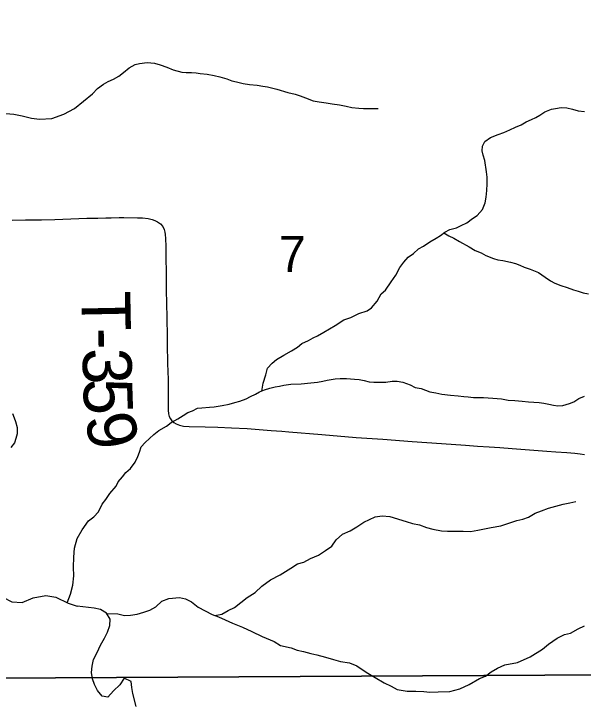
# Model space of a CAD drawing. Extents: x 1985906 to 2360102, y 891258 to 1222054.
# Drawn here: x 2141197 to 2144687, y 1014690 to 1018920 of the extents above; entities that cross this region are included whole.
import ezdxf

# ---------------------------------------------------------------- set-up
doc = ezdxf.new("R2010")
doc.units = 0
for name, color, linetype in [('GM_X_Minor_River', 7, 'Continuous'), ('GM_X_Section', 7, 'Continuous'), ('GM_X_Section_Text', 7, 'Continuous'), ('GM_X_Township_Road', 7, 'Continuous'), ('GM_X_Township_Road_Text', 7, 'Continuous')]:
    doc.layers.add(name, color=color, linetype=linetype)

msp = doc.modelspace()

# ---------------------------------------------------------------- linework, layer by layer
at = {"layer": 'GM_X_Minor_River'}
for points in [[(2141570.3, 1018340.4), (2141678.8, 1018430.1), (2141710.7, 1018462.5), (2141746.6, 1018488.9), (2141776.6, 1018505.2), (2141808.6, 1018519.5), (2141840.5, 1018537.9), (2141870.5, 1018560.2), (2141904.3, 1018588.6), (2141940.3, 1018608.9), (2141968.4, 1018615.2), (2142014.5, 1018621.6), (2142058.7, 1018617.9), (2142094.9, 1018606.2), (2142135.2, 1018592.5), (2142173.5, 1018576.7), (2142227.8, 1018563.1), (2142253.9, 1018559.3), (2142286, 1018559.6), (2142314.2, 1018557.8), (2142340.3, 1018554), (2142382.5, 1018550.3), (2142424.7, 1018542.6), (2142460.9, 1018532.9), (2142503.2, 1018521.2), (2142533.4, 1018509.4), (2142561.6, 1018503.6), (2142603.8, 1018491.9), (2142642, 1018486.2), (2142688.2, 1018482.6), (2142724.4, 1018476.8), (2142752.5, 1018473), (2142808.9, 1018457.4), (2142877.3, 1018437.9), (2142921.6, 1018428.2), (2142951.8, 1018416.4), (2142986, 1018404.7), (2143032.3, 1018387), (2143068.5, 1018381.3), (2143112.7, 1018373.6), (2143148.9, 1018367.9), (2143193.2, 1018362.2), (2143235.4, 1018354.5), (2143269.6, 1018346.8), (2143311.8, 1018341.1), (2143339.9, 1018339.3), (2143430.2, 1018340)], [(2141040.7, 1018290.3), (2141070.7, 1018298.6), (2141124.6, 1018311), (2141196.6, 1018305.5), (2141248.7, 1018293.9), (2141304.8, 1018280.3), (2141354.8, 1018274.7), (2141430.8, 1018279.3), (2141504.6, 1018305.9), (2141570.3, 1018340.4)], [(2142716.9, 1016608.6), (2142725.8, 1016657.8), (2142741.4, 1016708.1), (2142753.1, 1016748.4), (2142781, 1016778.7), (2142806.9, 1016801), (2142852.8, 1016827.5), (2142898.8, 1016856), (2142936.7, 1016878.4), (2142962.6, 1016900.7), (2143002.6, 1016919.1), (2143032.6, 1016935.4), (2143058.6, 1016947.6), (2143096.6, 1016970), (2143166.5, 1017010.8), (2143220.4, 1017045.3), (2143262.4, 1017059.7), (2143312.4, 1017084.2), (2143362.5, 1017100.7), (2143390.4, 1017119), (2143424.2, 1017159.4), (2143449.9, 1017203.8), (2143475.8, 1017226.1), (2143509.5, 1017278.6), (2143539.3, 1017319), (2143563, 1017365.4), (2143588.8, 1017397.7), (2143614.7, 1017428), (2143646.6, 1017450.4), (2143678.5, 1017480.7), (2143708.4, 1017497), (2143748.3, 1017523.5), (2143786.3, 1017545.9), (2143812.3, 1017562.2), (2143840.2, 1017582.4), (2143870.2, 1017598.8), (2143910.2, 1017609.1), (2143940.2, 1017623.4), (2143974.2, 1017639.8), (2144008.1, 1017666.2), (2144038.1, 1017684.5), (2144069.9, 1017720.9), (2144085.6, 1017761.2), (2144093.3, 1017797.3), (2144097, 1017837.5), (2144098.7, 1017877.7), (2144098.3, 1017919.9), (2144094, 1017951.9), (2144085.4, 1018020.1), (2144075.1, 1018054.2), (2144068.9, 1018080.2), (2144070.6, 1018108.4), (2144084.4, 1018136.6), (2144118.4, 1018161), (2144166.4, 1018179.4), (2144200.4, 1018191.8), (2144238.4, 1018208.1), (2144272.4, 1018224.5), (2144306.4, 1018238.8), (2144338.4, 1018257.1), (2144370.4, 1018271.4), (2144396.4, 1018283.7), (2144422.4, 1018298), (2144452.3, 1018318.3), (2144492.3, 1018334.7), (2144518.4, 1018338.9), (2144552.5, 1018345.2), (2144586.6, 1018343.5), (2144620.8, 1018335.7), (2144657, 1018326), (2144695.2, 1018320.3)], [(2143833, 1017577.2), (2143864.5, 1017558.6), (2143894.7, 1017544.8), (2143929, 1017525), (2143987.5, 1017491.3), (2144025.9, 1017469.5), (2144062.1, 1017455.8), (2144090.4, 1017439.9), (2144136.7, 1017420.2), (2144164.9, 1017412.4), (2144195, 1017408.7), (2144241.3, 1017399), (2144271.5, 1017389.2), (2144299.7, 1017379.4), (2144325.9, 1017367.6), (2144362.1, 1017355.8), (2144412.5, 1017334.2), (2144454.9, 1017306.4), (2144487.2, 1017284.6), (2144513.4, 1017268.7), (2144549.7, 1017255), (2144589.9, 1017243.2), (2144628.2, 1017229.5), (2144656.4, 1017219.7), (2144686.6, 1017209.9), (2144720.7, 1017204.2)], [(2141615.5, 1015759), (2141655.6, 1015813.7), (2141686.8, 1015838.2), (2141716.7, 1015868.5), (2141738.3, 1015914.9), (2141762.2, 1015945.2), (2141786, 1015981.5), (2141823.7, 1016026), (2141837.6, 1016052.2), (2141863.4, 1016082.5), (2141883.2, 1016108.8), (2141913.2, 1016133.1), (2141940.9, 1016173.5), (2141956.7, 1016207.8), (2141968.5, 1016234), (2141978.3, 1016266.2), (2142002.2, 1016292.5), (2142030, 1016318.8), (2142055.9, 1016343.1), (2142085.8, 1016367.4), (2142133.8, 1016393.9), (2142161.7, 1016416.3), (2142201.7, 1016438.7), (2142235.6, 1016459), (2142263.6, 1016477.3), (2142293.6, 1016487.6), (2142323.6, 1016503.9), (2142349.7, 1016506.1), (2142395.8, 1016510.5), (2142425.9, 1016512.8), (2142474, 1016519.2), (2142518.1, 1016527.6), (2142552.2, 1016537.9), (2142582.2, 1016546.2), (2142622.2, 1016560.6), (2142648.2, 1016574.8), (2142678.2, 1016589.1), (2142704.2, 1016603.4), (2142734.2, 1016615.7), (2142766.2, 1016626), (2142798.3, 1016634.3), (2142826.3, 1016638.5), (2142852.4, 1016644.8), (2142894.5, 1016651.2), (2142958.7, 1016653.7), (2143016.9, 1016658.2), (2143059, 1016662.5), (2143091.1, 1016668.8), (2143117.1, 1016675), (2143167.3, 1016683.5), (2143197.4, 1016685.8), (2143237.5, 1016686.1), (2143285.7, 1016680.4), (2143313.9, 1016678.7), (2143344, 1016672.9), (2143376.2, 1016665.1), (2143404.3, 1016663.3), (2143478.6, 1016664), (2143516.7, 1016668.3), (2143546.8, 1016668.5), (2143581, 1016662.8), (2143627.3, 1016647.1), (2143657.6, 1016631.3), (2143693.8, 1016623.5), (2143748.1, 1016603.9), (2143784.3, 1016598.2), (2143820.5, 1016590.5), (2143874.8, 1016582.9), (2143921, 1016579.2), (2143955.2, 1016575.5), (2143981.3, 1016573.7), (2144015.4, 1016570), (2144075.7, 1016568.4), (2144133.9, 1016564.9), (2144186.2, 1016561.3), (2144226.4, 1016553.6), (2144268.6, 1016549.9), (2144312.8, 1016546.3), (2144352.9, 1016542.6), (2144417.2, 1016539.1), (2144445.4, 1016535.3), (2144477.5, 1016527.6), (2144505.7, 1016521.8), (2144531.8, 1016518), (2144561.9, 1016520.2), (2144604, 1016532.6), (2144630, 1016542.9), (2144659.9, 1016563.2), (2144696, 1016577.5)], [(2141189.7, 1016471.3), (2141200.1, 1016445.3), (2141208.4, 1016421.4), (2141216.9, 1016385.4), (2141217.4, 1016347.3), (2141209.8, 1016317.1), (2141202.1, 1016290.9), (2141178.3, 1016262.5)], [(2142429, 1015234.2), (2142472.8, 1015242.2), (2142510.8, 1015264.6), (2142550.8, 1015283), (2142588.7, 1015313.5), (2142628.6, 1015343.9), (2142676.5, 1015374.4), (2142718.3, 1015412.9), (2142770.2, 1015451.5), (2142830.1, 1015482.1), (2142896, 1015522.8), (2142936, 1015549.2), (2142974, 1015559.6), (2143016, 1015582), (2143064, 1015602.5), (2143107.9, 1015630.9), (2143145.9, 1015657.3), (2143173.6, 1015697.7), (2143211.5, 1015732.2), (2143259.5, 1015752.6), (2143299.4, 1015777), (2143343.4, 1015805.5), (2143411.3, 1015838.2), (2143455.4, 1015844.6), (2143501.7, 1015841), (2143602.3, 1015809.7), (2143640.5, 1015797.9), (2143684.8, 1015788.2), (2143727.1, 1015772.5), (2143765.3, 1015762.8), (2143819.6, 1015753.2), (2143855.8, 1015749.5), (2143952.1, 1015750.3), (2143996.3, 1015748.6), (2144042.4, 1015757), (2144082.5, 1015765.4), (2144122.6, 1015771.7), (2144182.7, 1015782.3), (2144242.8, 1015802.8), (2144280.8, 1015815.2), (2144316.9, 1015823.5), (2144352.9, 1015835.9), (2144392.9, 1015860.3), (2144430.9, 1015874.7), (2144474.9, 1015891.1), (2144519, 1015903.5), (2144565.1, 1015915.9), (2144605.1, 1015924.3), (2144641.2, 1015932.6)], [(2141524.6, 1015311.7), (2141543.9, 1015364.2), (2141559.8, 1015420.3), (2141565.8, 1015476.4), (2141563.7, 1015530.5), (2141565.6, 1015590.6), (2141569.6, 1015646.7), (2141585.5, 1015704.8), (2141615.5, 1015759)], [(2141019.9, 1015413.6), (2141034.5, 1015400.4), (2141131, 1015345.5), (2141185.2, 1015317.9), (2141249.2, 1015312.3), (2141315, 1015340.9), (2141392.9, 1015355.5), (2141454.9, 1015345.9), (2141531.2, 1015308.4), (2141585.3, 1015290.8)], [(2141767.4, 1015246.3), (2141834.4, 1015243), (2141876.6, 1015233.3), (2141912.8, 1015235.7), (2141952.9, 1015242), (2141994.9, 1015254.4), (2142030.9, 1015266.7), (2142066.9, 1015287.1), (2142104.8, 1015321.5), (2142146.8, 1015338), (2142213, 1015344.5), (2142249.2, 1015334.8), (2142285.5, 1015317), (2142327.9, 1015285.2), (2142370.3, 1015261.5), (2142412.6, 1015239.8), (2142452.9, 1015226), (2142493.2, 1015206.3), (2142537.5, 1015186.6), (2142600, 1015163), (2142656.4, 1015135.3), (2142718.9, 1015105.7), (2142793.5, 1015074.2), (2142831.8, 1015050.4), (2142898.2, 1015034.9), (2142934.4, 1015021.2), (2142972.7, 1015013.4), (2143016.9, 1014999.7), (2143055.2, 1014992), (2143107.5, 1014978.4), (2143155.8, 1014964.7), (2143200, 1014951), (2143254.3, 1014943.4), (2143300.6, 1014925.8), (2143357.2, 1014886.1), (2143468.2, 1014820.7), (2143510.5, 1014801), (2143546.8, 1014779.2), (2143609.1, 1014769.7), (2143661.3, 1014770.1), (2143711.5, 1014768.5), (2143747.7, 1014764.8), (2143797.9, 1014765.2), (2143870.1, 1014767.8), (2143930.2, 1014784.3), (2143988.2, 1014810.9), (2144052.1, 1014847.6), (2144088.2, 1014861.9), (2144124.1, 1014888.3), (2144162, 1014910.7), (2144208, 1014931.2), (2144284.2, 1014945.8), (2144362.2, 1014980.6), (2144438.1, 1015027.4), (2144474, 1015057.8), (2144527.9, 1015094.4), (2144571.8, 1015116.9), (2144609.9, 1015125.2), (2144655.9, 1015151.7), (2144695.9, 1015170.1)], [(2141947.6, 1014675.8), (2141926.9, 1014755.9), (2141920.5, 1014792), (2141916.2, 1014830.1), (2141873.9, 1014849.8), (2141848.1, 1014809.5), (2141808.3, 1014771), (2141774.5, 1014732.6), (2141738.3, 1014738.3), (2141709.9, 1014774.2), (2141691.5, 1014810.2), (2141679.2, 1014846.2), (2141672.8, 1014884.3), (2141678.5, 1014922.5), (2141686.2, 1014964.8), (2141707.9, 1015007.1), (2141729.6, 1015051.4), (2141753.4, 1015093.8), (2141771.1, 1015132.1), (2141786.8, 1015172.4), (2141788.5, 1015210.5), (2141766.1, 1015248.5), (2141727.8, 1015270.3), (2141690, 1015278.3), (2141654.3, 1015281.7), (2141585.3, 1015290.8)]]:
    msp.add_lwpolyline(points, dxfattribs=at)
at = {"layer": 'GM_X_Section'}
for points in [[(2141007.1, 1020154.3), (2144733.4, 1020193.5), (2144828.1, 1014870.9), (2141074.1, 1014849.6), (2141073.8, 1014909.6)], [(2141074.1, 1014849.6), (2144828.1, 1014870.9), (2144878.5, 1009582.1), (2141132.9, 1009584.8)]]:
    msp.add_lwpolyline(points, close=True, dxfattribs=at)
at = {"layer": 'GM_X_Township_Road'}
for points in [[(2141187.7, 1017656.4), (2141269.5, 1017656.9), (2141367.5, 1017657.1), (2141449.2, 1017659.7), (2141645.9, 1017667), (2141711.5, 1017668.3), (2141760.7, 1017669), (2141793.5, 1017669.7), (2141842.3, 1017671.2), (2141872.7, 1017672.2), (2141955.8, 1017670.4), (2141987, 1017669.5), (2142020, 1017666), (2142046, 1017659.9), (2142062.5, 1017653.9), (2142079, 1017646), (2142097.3, 1017632.2), (2142110.3, 1017616.5), (2142119, 1017599.1), (2142123.3, 1017582.6), (2142125.9, 1017568.7), (2142126.8, 1017542.7), (2142128.5, 1017493.2), (2142129.4, 1017422), (2142130.2, 1017336.1), (2142130.9, 1017263.1), (2142131.6, 1017220.6), (2142132.9, 1017150.3), (2142134.6, 1017053), (2142136.5, 1016947), (2142137.8, 1016874.1), (2142139.1, 1016800.3), (2142139.5, 1016777.3), (2142142.6, 1016679.2), (2142142.6, 1016564.2), (2142143.4, 1016515), (2142143.9, 1016491.2), (2142145.7, 1016469.1), (2142150.4, 1016453.6), (2142157.5, 1016439.1), (2142166.2, 1016426.7), (2142177.3, 1016416.6), (2142192.1, 1016406.8), (2142213.3, 1016398.8), (2142237.2, 1016393.7), (2142271.2, 1016391.3), (2142370.4, 1016390.3), (2142447.7, 1016388.2), (2142531.2, 1016383.6), (2142627.3, 1016378.3), (2142774, 1016366.6), (2142839.4, 1016362.7), (2142883.9, 1016359)], [(2142883.9, 1016359), (2143084.4, 1016342.5), (2143296.4, 1016324.9), (2143459.9, 1016313.9), (2143639.7, 1016300.1), (2143819.6, 1016288.1), (2143966.6, 1016277.2), (2144039.4, 1016271.9), (2144110.7, 1016266.7), (2144177.3, 1016261.8), (2144252.9, 1016256.2), (2144330.9, 1016250.7), (2144384.1, 1016246.9), (2144464.7, 1016241.2), (2144520.4, 1016237.2), (2144586.7, 1016232.5), (2144635.5, 1016228.2), (2144668, 1016224.2), (2144695.8, 1016219.8)]]:
    msp.add_lwpolyline(points, dxfattribs=at)

# ---------------------------------------------------------------- texts
at = {"layer": 'GM_X_Section_Text'}
msp.add_text('7', height=221, rotation=0, dxfattribs=at).set_placement((2142822.5, 1017338.4))
at = {"layer": 'GM_X_Township_Road_Text'}
for s, rotation, p in [('T', 271.1315, (2141611, 1017218.2)), ('-', 271.165, (2141615.5, 1016993.7)), ('3', 271.291, (2141618, 1016869.8)), ('5', 271.8512, (2141622.3, 1016681.8)), ('9', 280.0224, (2141633.1, 1016450.8))]:
    msp.add_text(s, height=300, rotation=rotation, dxfattribs=at).set_placement(p)

doc.saveas('drawing.dxf')
